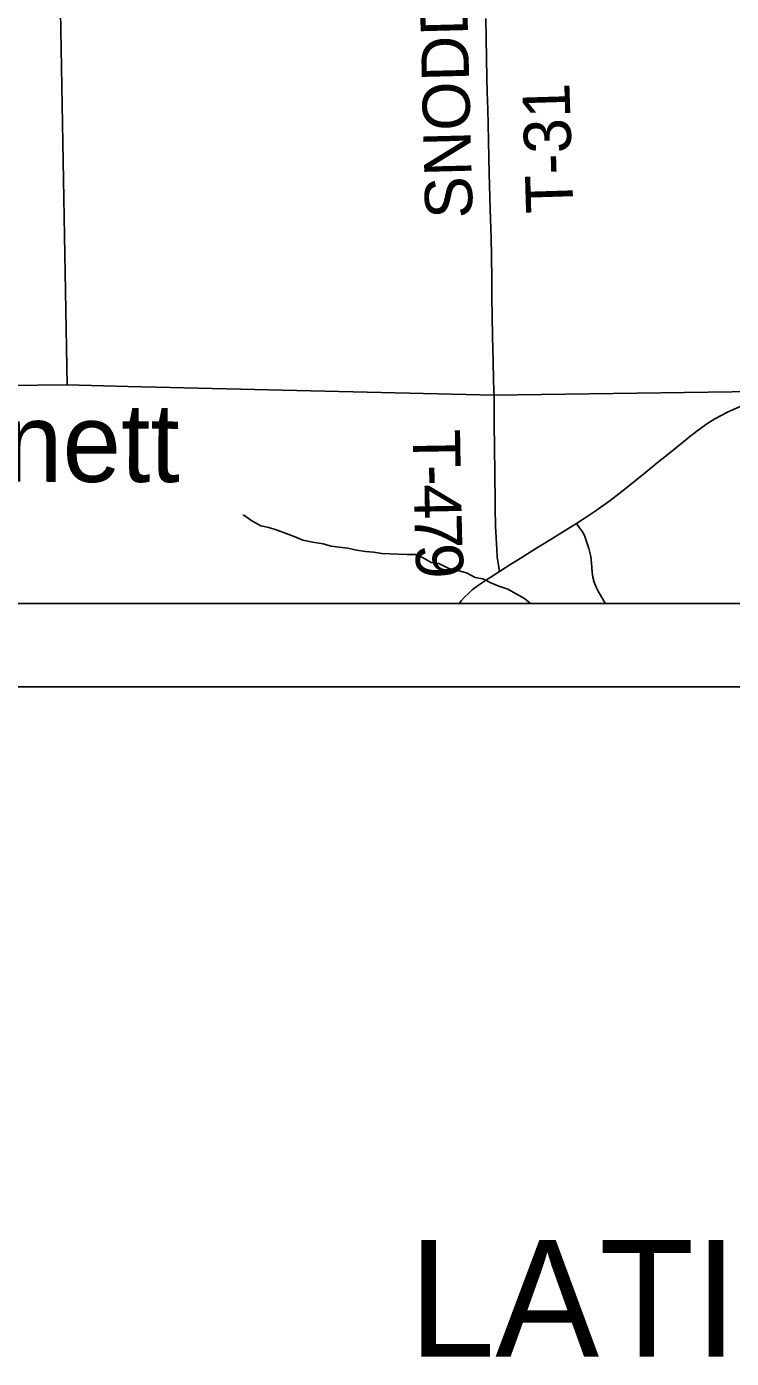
# Model space of a CAD drawing. Extents: x 0 to 34, y 0 to 22.
# Drawn here: x 2.612 to 3.459, y 13.194 to 14.792 of the extents above; entities that cross this region are included whole.
import ezdxf

# ---------------------------------------------------------------- set-up
doc = ezdxf.new("R2010")
doc.units = 0
for name, color, linetype in [('Default', 7, 'Continuous'), ('GM_X_Minor_Lake_Text', 7, 'Continuous'), ('GM_X_Minor_River', 7, 'Continuous'), ('GM_X_State_Route', 7, 'Continuous'), ('GM_X_Township_Road', 7, 'Continuous'), ('GM_X_Township_Road_Text', 7, 'Continuous'), ('SH_Cut_Line', 7, 'Continuous'), ('SH_Data', 7, 'Continuous'), ('SH_Text', 7, 'Continuous')]:
    doc.layers.add(name, color=color, linetype=linetype)

msp = doc.modelspace()

# ---------------------------------------------------------------- linework, layer by layer
at = {"layer": 'Default'}
for points in [[(2.1, 18.375), (2.1, 14.3539), (2.1651, 14.3567), (2.6607, 14.3625), (2.6434, 15.3487), (2.6428, 15.3713), (2.6388, 15.4856), (2.6332, 16.3685), (2.6231, 17.3771), (2.6129, 17.8818), (2.6122, 18.05), (2.6118, 18.3803)], [(2.1, 14.3539), (2.1, 14.1), (3.6803, 14.1), (3.6708, 14.3479), (3.5171, 14.3547), (3.1736, 14.3499), (2.7339, 14.3605), (2.6607, 14.3625), (2.1651, 14.3567)]]:
    msp.add_lwpolyline(points, close=True, dxfattribs=at)
msp.add_lwpolyline([(2.6231, 17.3771), (2.6332, 16.3685), (2.6388, 15.4856), (2.6428, 15.3713), (2.6434, 15.3487), (2.6607, 14.3625), (2.7339, 14.3605), (3.1736, 14.3499), (3.5171, 14.3547), (3.6708, 14.3479), (4.282, 14.3483), (4.5209, 14.3512)], dxfattribs=at)
at = {"layer": 'GM_X_Minor_River'}
msp.add_lwpolyline([(3.2176, 14.1), (3.2101, 14.1057), (3.1903, 14.1169), (3.1796, 14.1207), (3.1698, 14.1248), (3.1603, 14.1293), (3.1508, 14.1311), (3.1405, 14.1367), (3.1287, 14.1397), (3.1192, 14.1419), (3.1075, 14.1479), (3.098, 14.149), (3.0885, 14.1546), (3.079, 14.1587), (3.0691, 14.1586), (3.0585, 14.1593), (3.0388, 14.16), (3.0289, 14.1614), (3.0191, 14.1625), (3.0085, 14.164), (2.9982, 14.1662), (2.9876, 14.1676), (2.9781, 14.1687), (2.9683, 14.1717), (2.958, 14.1731), (2.944, 14.1761), (2.9337, 14.1805), (2.9238, 14.1839), (2.9132, 14.188), (2.9033, 14.1913), (2.8935, 14.1932), (2.8828, 14.1992), (2.8729, 14.2059), (2.8718, 14.2056)], dxfattribs=at)
at = {"layer": 'GM_X_State_Route'}
msp.add_lwpolyline([(3.1316, 14.1), (3.1342, 14.1032), (3.1384, 14.1077), (3.1428, 14.1119), (3.1475, 14.1161), (3.1551, 14.1217), (3.1635, 14.1275), (3.1733, 14.1338), (3.1802, 14.1381), (3.1938, 14.1469), (3.207, 14.1551), (3.2227, 14.1652), (3.2412, 14.1765), (3.2623, 14.1895), (3.2729, 14.1961), (3.2808, 14.2011), (3.2962, 14.2116), (3.3114, 14.2225), (3.3286, 14.2357), (3.3433, 14.2473), (3.3556, 14.2573), (3.3698, 14.2687), (3.3843, 14.2805), (3.4084, 14.3), (3.4171, 14.3068), (3.4232, 14.3113), (3.4303, 14.3163), (3.4389, 14.3216), (3.4551, 14.33), (3.4693, 14.3364)], dxfattribs=at)
at = {"layer": 'GM_X_Township_Road'}
for points in [[(3.1738, 14.3493), (3.1735, 14.3558), (3.1731, 14.3682), (3.1726, 14.3899), (3.172, 14.4209), (3.1712, 14.4674), (3.1709, 14.4891), (3.1705, 14.517), (3.1701, 14.5387), (3.1691, 14.5728), (3.168, 14.6162), (3.1676, 14.6351), (3.1665, 14.6751), (3.1661, 14.693), (3.1654, 14.7137), (3.1649, 14.7309), (3.1642, 14.7779), (3.1637, 14.802)], [(3.1802, 14.1381), (3.1791, 14.1457), (3.1775, 14.1556), (3.1769, 14.1652), (3.1756, 14.1925), (3.1751, 14.2142), (3.1746, 14.2637), (3.1743, 14.2798), (3.174, 14.3226), (3.1738, 14.3493)], [(3.3075, 14.1), (3.3057, 14.103), (3.299, 14.114), (3.2962, 14.1196), (3.2941, 14.1255), (3.2925, 14.1315), (3.2915, 14.1376), (3.2908, 14.1484), (3.2899, 14.1562), (3.2877, 14.1658), (3.2849, 14.1744), (3.2827, 14.1803), (3.2814, 14.1831), (3.2798, 14.1858), (3.2764, 14.1909), (3.2729, 14.1961)]]:
    msp.add_lwpolyline(points, dxfattribs=at)
at = {"layer": 'SH_Cut_Line'}
msp.add_lwpolyline([(2.6032, 20.9), (2.1, 20.9), (2.1, 14.3539), (2.1651, 14.3567), (2.6607, 14.3625), (2.6434, 15.3487), (2.6428, 15.3713), (2.6388, 15.4856), (2.6332, 16.3685), (2.6231, 17.3771), (2.6129, 17.8818), (2.6122, 18.05), (2.6118, 18.3803), (2.6161, 18.3799), (2.6204, 18.3797), (2.6263, 18.3795), (2.6292, 18.3794), (2.6281, 18.8843), (2.6224, 19.9515), (2.6032, 20.8721)], close=True, dxfattribs=at)
for points in [[(2.6231, 17.3771), (2.6332, 16.3685), (2.6388, 15.4856), (2.6428, 15.3713), (2.6434, 15.3487), (2.6607, 14.3625), (2.7339, 14.3605), (3.1736, 14.3499), (3.5171, 14.3547), (3.6708, 14.3479), (4.282, 14.3483), (4.5209, 14.3512)], [(4.5209, 14.3512), (4.282, 14.3483), (3.6708, 14.3479), (3.5171, 14.3547), (3.1736, 14.3499), (2.7339, 14.3605), (2.6607, 14.3625), (2.1651, 14.3567)], [(2.1, 14.1), (8.9, 14.1)]]:
    msp.add_lwpolyline(points, dxfattribs=at)
at = {"layer": 'SH_Data'}
for p, q in [((2.1, 14.1), (8.9, 14.1)), ((2, 14), (9, 14))]:
    msp.add_line(p, q, dxfattribs=at)

# ---------------------------------------------------------------- texts
at = {"layer": 'GM_X_Minor_Lake_Text'}
msp.add_text('Bonnett', height=0.09471, rotation=359.8803, dxfattribs=at).set_placement((2.3594, 14.2465))
at = {"layer": 'GM_X_Township_Road_Text'}
for s, height, rotation, p in [('SNODDY', 0.05682, 91.4671, (3.1481, 14.5625)), ('T-31', 0.05682, 91.7854, (3.269, 14.5691)), ('T', 0.0568, 270.9986, (3.076, 14.3085)), ('-', 0.0568, 271.0096, (3.0768, 14.266)), ('4', 0.0568, 271.0825, (3.0772, 14.2426)), ('7', 0.0568, 271.3464, (3.0779, 14.2074)), ('9', 0.0568, 273.0543, (3.0788, 14.1705))]:
    msp.add_text(s, height=height, rotation=rotation, dxfattribs=at).set_placement(p)
at = {"layer": 'SH_Text'}
msp.add_text('LATITUDE:  N40°43\'20"     LONGITUDE:  W82°03\'26"', height=0.14, dxfattribs=at).set_placement((3.071, 13.1958))

doc.saveas('drawing.dxf')
